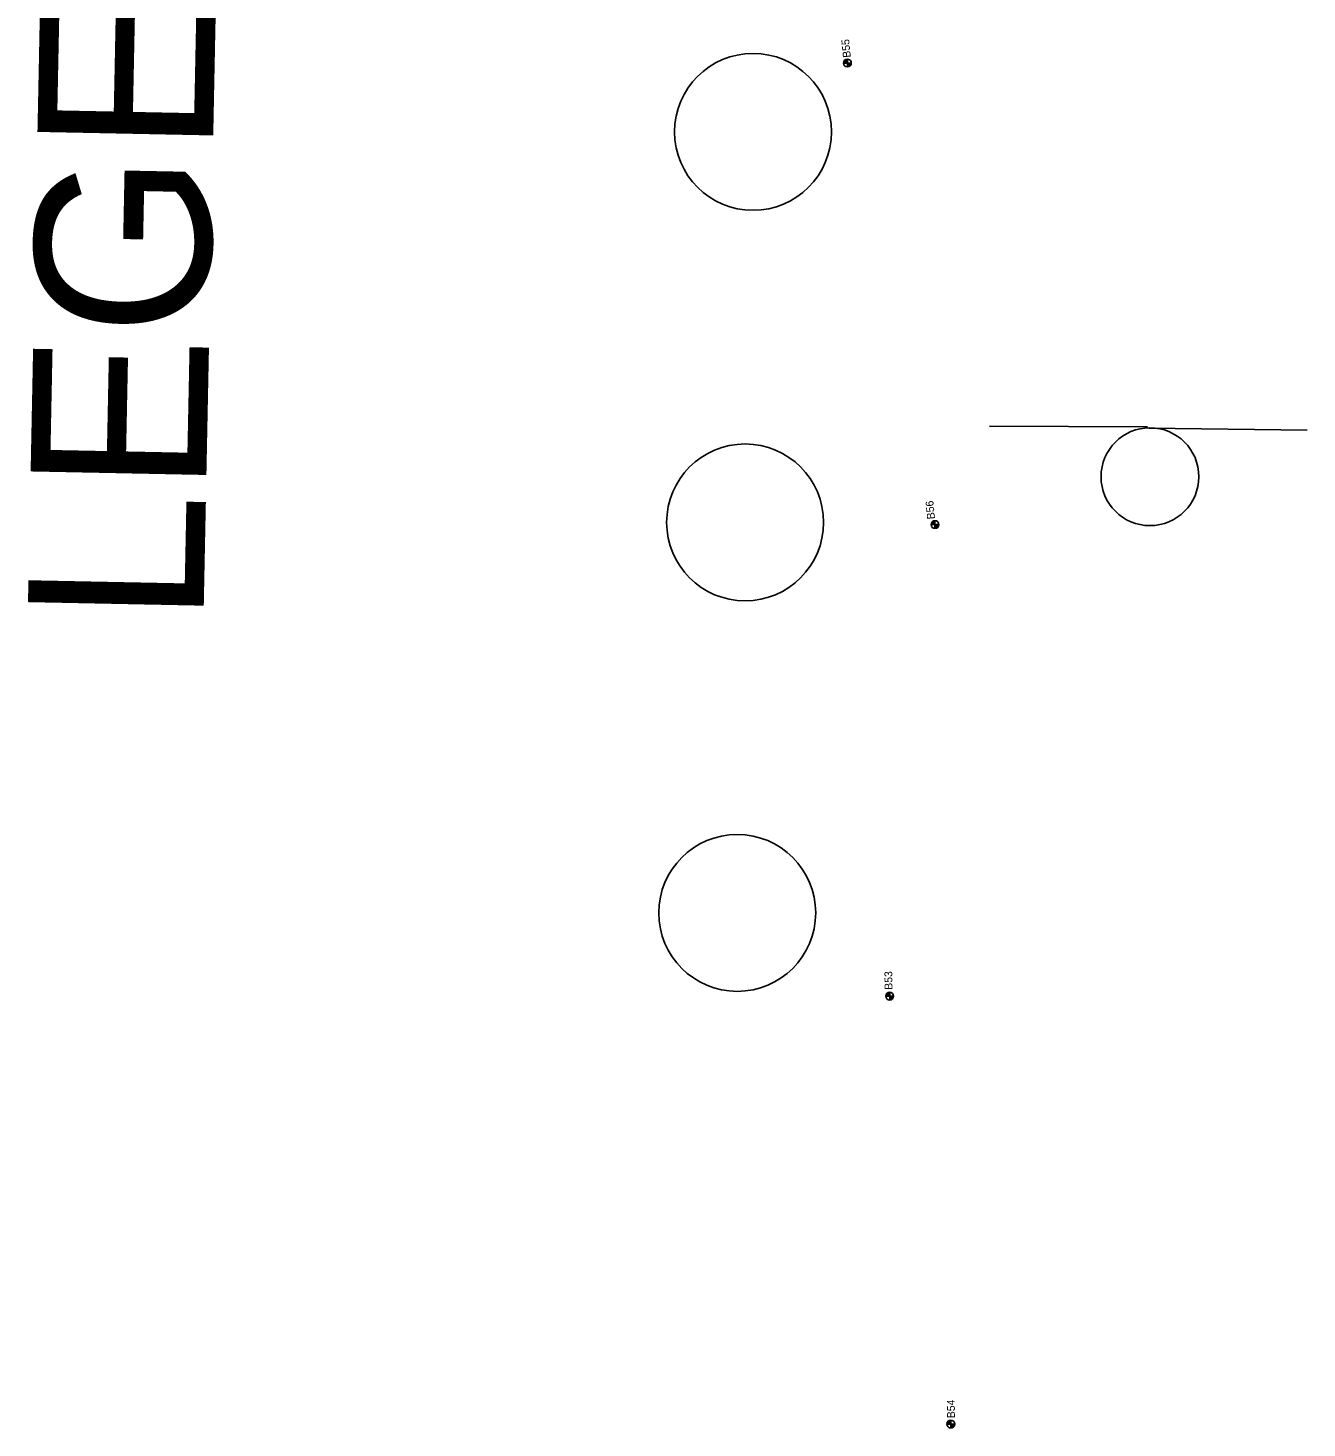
# Model space of a CAD drawing. Extents: x 335726 to 369746, y 119154 to 200788.
# Drawn here: x 359088 to 360724, y 158779 to 160571 of the extents above; entities that cross this region are included whole.
import ezdxf

# ---------------------------------------------------------------- set-up
doc = ezdxf.new("R2010")
doc.units = 0
for name, color, linetype in [('CA-TEXT', 7, 'Continuous'), ('E_SOIL_BORE1 [KAPUR_CADDS_LEVELS]', 7, 'Continuous'), ('E_SOIL_BORE2 [KAPUR_CADDS_LEVELS]', 7, 'Continuous'), ('P_MARK', 7, 'Continuous'), ('PLT_Sheet_Info', 7, 'Continuous'), ('SIGNS-POLES', 7, 'Continuous')]:
    doc.layers.add(name, color=color, linetype=linetype)

msp = doc.modelspace()

# ---------------------------------------------------------------- linework, layer by layer
at = {"layer": 'P_MARK'}
for p, q in [((360131.3, 160526.6), (360141.3, 160526.6)), ((360136.3, 160531.6), (360136.3, 160521.6)), ((360243.3, 159935.8), (360253.3, 159935.8)), ((360248.3, 159940.8), (360248.3, 159930.8)), ((360190.4, 159337.2), (360190.4, 159327.2)), ((360185.4, 159332.2), (360195.4, 159332.2)), ((360263.6, 158784.4), (360273.6, 158784.4)), ((360268.6, 158789.4), (360268.6, 158779.4))]:
    msp.add_line(p, q, dxfattribs=at)
for centre in [(360136.3, 160526.6), (360248.3, 159935.8), (360190.4, 159332.2), (360268.6, 158784.4)]:
    msp.add_circle(centre, 5, dxfattribs=at)
for centre, radius, start, end in [((360136.3, 160526.6), 4.5, 89.9869, 179.9869), ((360136.3, 160526.6), 4, 89.9869, 179.9869), ((360136.3, 160526.6), 3.5, 89.9869, 179.9869), ((360136.3, 160526.6), 3, 89.9869, 179.9869), ((360136.3, 160526.6), 2.5, 89.9869, 179.9869), ((360136.3, 160526.6), 2, 89.9869, 179.9869), ((360136.3, 160526.6), 1.5, 89.9869, 179.9869), ((360136.3, 160526.6), 1, 89.9869, 179.9869), ((360136.3, 160526.6), 0.5, 89.9869, 179.9869), ((360136.3, 160526.6), 4.5, 269.9869, 359.9869), ((360136.3, 160526.6), 4, 269.9869, 359.9869), ((360136.3, 160526.6), 3.5, 269.9869, 359.9869), ((360136.3, 160526.6), 3, 269.9869, 359.9869), ((360136.3, 160526.6), 2.5, 269.9869, 359.9869), ((360136.3, 160526.6), 2, 269.9869, 359.9869), ((360136.3, 160526.6), 1.5, 269.9869, 359.9869), ((360136.3, 160526.6), 1, 269.9869, 359.9869), ((360136.3, 160526.6), 0.5, 269.9869, 359.9869), ((360248.3, 159935.8), 4.5, 89.9869, 179.9869), ((360248.3, 159935.8), 4, 89.9869, 179.9869), ((360248.3, 159935.8), 3.5, 89.9869, 179.9869), ((360248.3, 159935.8), 3, 89.9869, 179.9869), ((360248.3, 159935.8), 2.5, 89.9869, 179.9869), ((360248.3, 159935.8), 2, 89.9869, 179.9869), ((360248.3, 159935.8), 1.5, 89.9869, 179.9869), ((360248.3, 159935.8), 1, 89.9869, 179.9869), ((360248.3, 159935.8), 0.5, 89.9869, 179.9869), ((360248.3, 159935.8), 4.5, 269.9869, 359.9869), ((360248.3, 159935.8), 4, 269.9869, 359.9869), ((360248.3, 159935.8), 3.5, 269.9869, 359.9869), ((360248.3, 159935.8), 3, 269.9869, 359.9869), ((360248.3, 159935.8), 2.5, 269.9869, 359.9869), ((360248.3, 159935.8), 2, 269.9869, 359.9869), ((360248.3, 159935.8), 1.5, 269.9869, 359.9869), ((360248.3, 159935.8), 1, 269.9869, 359.9869), ((360248.3, 159935.8), 0.5, 269.9869, 359.9869), ((360190.4, 159332.2), 4.5, 89.9869, 179.9869), ((360190.4, 159332.2), 4, 89.9869, 179.9869), ((360190.4, 159332.2), 3.5, 89.9869, 179.9869), ((360190.4, 159332.2), 3, 89.9869, 179.9869), ((360190.4, 159332.2), 2.5, 89.9869, 179.9869), ((360190.4, 159332.2), 2, 89.9869, 179.9869), ((360190.4, 159332.2), 1.5, 89.9869, 179.9869), ((360190.4, 159332.2), 1, 89.9869, 179.9869), ((360190.4, 159332.2), 0.5, 89.9869, 179.9869), ((360190.4, 159332.2), 4.5, 269.9869, 359.9869), ((360190.4, 159332.2), 4, 269.9869, 359.9869), ((360190.4, 159332.2), 3.5, 269.9869, 359.9869), ((360190.4, 159332.2), 3, 269.9869, 359.9869), ((360190.4, 159332.2), 2.5, 269.9869, 359.9869), ((360190.4, 159332.2), 2, 269.9869, 359.9869), ((360190.4, 159332.2), 1.5, 269.9869, 359.9869), ((360190.4, 159332.2), 1, 269.9869, 359.9869), ((360190.4, 159332.2), 0.5, 269.9869, 359.9869), ((360268.6, 158784.4), 4.5, 89.9869, 179.9869), ((360268.6, 158784.4), 4, 89.9869, 179.9869), ((360268.6, 158784.4), 3.5, 89.9869, 179.9869), ((360268.6, 158784.4), 3, 89.9869, 179.9869), ((360268.6, 158784.4), 2.5, 89.9869, 179.9869), ((360268.6, 158784.4), 2, 89.9869, 179.9869), ((360268.6, 158784.4), 1.5, 89.9869, 179.9869), ((360268.6, 158784.4), 1, 89.9869, 179.9869), ((360268.6, 158784.4), 0.5, 89.9869, 179.9869), ((360268.6, 158784.4), 4.5, 269.9869, 359.9869), ((360268.6, 158784.4), 4, 269.9869, 359.9869), ((360268.6, 158784.4), 3.5, 269.9869, 359.9869), ((360268.6, 158784.4), 3, 269.9869, 359.9869), ((360268.6, 158784.4), 2.5, 269.9869, 359.9869), ((360268.6, 158784.4), 2, 269.9869, 359.9869), ((360268.6, 158784.4), 1.5, 269.9869, 359.9869), ((360268.6, 158784.4), 1, 269.9869, 359.9869), ((360268.6, 158784.4), 0.5, 269.9869, 359.9869)]:
    msp.add_arc(centre, radius, start, end, dxfattribs=at)
at = {"layer": 'PLT_Sheet_Info'}
for centre in [(360015.5, 160438.5), (360005.4, 159938.6), (359995.3, 159438.7)]:
    msp.add_circle(centre, 100.4, dxfattribs=at)
at = {"layer": 'SIGNS-POLES'}
for p, q in [((360317.9, 160061.9), (360520.4, 160060.9)), ((360521.9, 160059.3), (360724.4, 160056.8))]:
    msp.add_line(p, q, dxfattribs=at)
msp.add_circle((360523.4, 159997.1), 62.6, dxfattribs=at)

# ---------------------------------------------------------------- texts
at = {"layer": 'CA-TEXT'}
msp.add_text('LEGEND', height=225, rotation=88.8468, dxfattribs=at).set_placement((359312.2, 159807.3))
at = {"layer": 'E_SOIL_BORE1 [KAPUR_CADDS_LEVELS]'}
for s, p in [('B53', (360193.9, 159340.4)), ('B54', (360273.9, 158792))]:
    msp.add_text(s, height=10, rotation=90.6368, dxfattribs=at).set_placement(p)
at = {"layer": 'E_SOIL_BORE2 [KAPUR_CADDS_LEVELS]'}
for s, p in [('B55', (360140.7, 160533.9)), ('B56', (360248.4, 159943.1))]:
    msp.add_text(s, height=10, rotation=95.5802, dxfattribs=at).set_placement(p)

doc.saveas('drawing.dxf')
